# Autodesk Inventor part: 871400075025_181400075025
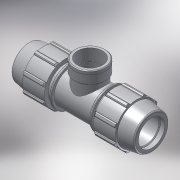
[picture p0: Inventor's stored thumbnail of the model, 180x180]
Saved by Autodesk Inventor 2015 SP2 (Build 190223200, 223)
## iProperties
Created: 2017-02
Part Number: 871400075025_181400075025
Material: PVC-Piping
Description: PLASSON TEE WITH THREADED FEMALE OFFTAKE 75-2.1/2"-75
Document SubType Name: Modeling
Designer: KIM
Mass: 92.6774 g
Surface Area: 199.44 cm^2
Volume: 66.1981 cm^3
Density: 1.4 g/cm^3
Appearance: Smooth - White
Author: KIM
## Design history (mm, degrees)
derived "87140.ipt"
feature "Solid1::87140.ipt"
feature "Solid2::87140.ipt"
tag "TaggingFeature1"
body "Solid1"
other parameters: "d2" = 75, "d4" = 14.25, "d5" = 41.04, "d7" = 132, "d11" = 5.7, "d13" = 120 deg, "d14" = 97.5, "d15" = 12 deg, "d16" = 114.84, "d18" = 3.75, "d19" = 35 deg, "d20" = 17.5 deg, "d21" = 122.76, "d23" = 0, "d25" = 360 deg, "d27" = 2.64, "d33" = 1.5, "d42" = 61.56, "d43" = 3.96, "d46" = 2.25, "d68" = 10.26, "d72" = 85, "d76" = 72.226, "d80" = 2.16678, "d91" = 99, "d93" = 134, "d95" = 67.5, "d112" = 35, "d115" = 90.2825, "d116" = 135 deg, "d117" = 83.0599, "d118" = 342, "d119" = 67.5, "d121" = 0, "d122" = 67.5, "d124" = 0, "d128" = 0, "d129" = 7.5, "d130" = 10.5, "d131" = 0.3, "d132" = 0.3, "d133" = 90.2825, "d_" = 75, "E_" = 132, "A_" = 85, "l_" = 134, "l_2" = 35, "Rp_" = 72.226, "H_" = 342
